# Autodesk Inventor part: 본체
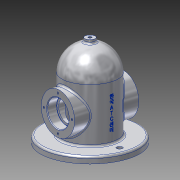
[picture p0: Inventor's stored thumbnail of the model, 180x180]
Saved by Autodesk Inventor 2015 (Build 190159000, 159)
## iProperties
Created: 2019-11
Part Number: 본체
Material: 알루미늄 6061
Document SubType Name: Modeling
Designer: LINEART-SSD.D4.16.06
Density: 2.7 g/cm^3
Appearance: 알루미늄 - 평지
Mass: 1106.13 g
Surface Area: 883.263 cm^2
Volume: 409.676 cm^3
Author: LINEART-SSD.D4.16.06
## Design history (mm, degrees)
sketch "스케치1"
  geometry: C1 r 70 at (0, 0); 1 further point
  constraints: 1 centre point, 1 coincident
  dimensions: "d0" = 140 diameter of C1
extrude "돌출1" new body sketch "스케치1" distance "d1" = 10; taper "d2" = 0 deg
sketch "스케치2"
  geometry: L1 (81, 50)-(50, 50); L2 (50, 50)-(50, -50); L3 (50, -50)-(81, -50); L4 (81, -50)-(81, 50); 2 further points
  constraints: 8 end point, 2 parallel, 1 horizontal, 1 horizontal alignment, 1 midpoint, 1 perpendicular
  dimensions: "d3" = 50 distance from line of L2 point (0, 0); "d4" = 100 distance of L3.end L1.start; "d5" = 62 diameter of L4 L2
revolve "회전1" sketch "스케치2" stored, may be unused: angle "d6" = 90 deg
sketch "스케치3"
  geometry: C1 r 40 at (0, 0); 1 further point
  constraints: 1 centre point, 1 coincident
  dimensions: "d7" = 80 diameter of C1
extrude "돌출2" join sketch "스케치3" distance "d8" = 80; taper "d9" = 0 deg
sketch "스케치4"
  geometry: L1 (90, -40)-(90, 40) reference; L2 (90, 0)-(130, 0); L3 (90, 0)-(90, -40); L4 (130, 0)-(90, 0); L5 (90, 0)-(90, -40); A1 r 40 centre (90, 0) between (90, -40) and (130, 0); 1 further point
  constraints: 8 end point, 2 point on circle, 1 centre point, 1 collinear, 1 horizontal alignment, 1 midpoint, 1 point on line
  dimensions: "d10" = 40 radius of A1; "d11" = 90 deg angle of L3 L2
revolve "회전2" sketch "스케치4" stored, may be unused: angle "d12" = 90 deg
sketch "스케치5"
  geometry: C1 r 30 at (0, 0); 1 further point
  constraints: 1 centre point, 1 coincident
  dimensions: "d13" = 60 diameter of C1
extrude "돌출3" cut sketch "스케치5" distance "d14" = 90; taper "d15" = 0 deg
sketch "스케치6"
  geometry: L1 (90, -30)-(90, 30) reference; L2 (0, -30)-(0, 30) reference; L3 (90, 0)-(120, 0); L4 (90, 0)-(90, -30); L5 (120, 0)-(90, 0); L6 (90, 0)-(90, -30); A1 r 30 centre (90, 0) between (90, -30) and (120, 0); 1 further point
  constraints: 8 end point, 2 point on circle, 1 centre point, 1 collinear, 1 midpoint
  dimensions: "d16" = 30 radius of A1 (derived); "d17" = 90 deg angle of L4 L3
revolve "회전3" sketch "스케치6" stored, may be unused: angle "d18" = 90 deg
sketch "스케치7"
  geometry: L1 (70, 50)-(70, 35.3); L2 (69.7, 35)-(66.5, 35); L3 (66.5, 35)-(66.5, -35); L4 (66.5, -35)-(69.7, -35); L5 (0, -30)-(90, -30) reference; L6 (70, -35.3)-(70, -50); L7 (70, -50)-(50, -50); L8 (50, -50)-(50, 50); L9 (50, 50)-(70, 50); A1 r 0.3 centre (69.7, 35.3) between (69.7, 35) and (70, 35.3); A2 r 0.3 centre (69.7, -35.3) between (70, -35.3) and (69.7, -35); 4 further points
  constraints: 16 end point, 6 perpendicular, 4 point on circle, 4 point on line, 4 tangent, 2 centre point, 1 equal radius, 1 horizontal alignment, 1 midpoint, 1 parallel, 1 vertical
  dimensions: "d19" = 15 distance of L1.start point (70, 35); "d20" = 15 distance of point (70, -35) L6.end; "d21" = 100 distance of L7.end L8.end; "d22" = 50 distance from line of point (0, 0) L8; "d23" = 33 diameter of L3 L8; "d24" = 40 diameter of L1 L8; "d25" = 40 diameter of L6 L8; "d26" = 0.3 radius of A1
revolve "회전4" sketch "스케치7" stored, may be unused: angle "d27" = 90 deg
sketch "스케치8"
  geometry: C1 r 20 at (0, 0) reference; C2 r 31 at (0, 0) reference; 2 further points
  constraints: 1 vertical alignment
  dimensions: "d28" = 26 distance of point (0, 26) C1.centre
hole "구멍1" sketch "스케치8" at (0, 26) diameter "d29" = 3.242; stored, may be unused: countersink angle "d33" = 90 deg, drill point angle "d35" = 118 deg; dims "d30" = 8, "d31" = 4, "d32" = 2, "d34" = 10
node "작업 평면1"
node "작업 평면2"
sketch "스케치9"
  geometry: C1 r 7.5 at (0, 0); 1 further point
  constraints: 1 centre point, 1 coincident
  dimensions: "d39" = 15 diameter of C1
extrude "돌출4" join sketch "스케치9" stored distance "d40" = 10; taper "d41" = 0 deg
sketch "스케치10"
  geometry: C1 r 7.5 at (0, 0) reference; 2 further points
  constraints: 1 coincident
hole "구멍2" sketch "스케치10" at (0, 0) diameter "d42" = 5.188; stored, may be unused: countersink angle "d46" = 90 deg, drill point angle "d48" = 118 deg; dims "d43" = 12, "d44" = 4, "d45" = 2, "d47" = 16
sketch "스케치11"
  geometry: C1 r 70 at (0, 0) reference; 2 further points
  constraints: 1 horizontal alignment
  dimensions: "d49" = 55 distance of point (0, 0) point (-55, 0)
hole "구멍3" sketch "스케치11" at (-55, 0) diameter "d50" = 9; stored, may be unused: countersink angle "d54" = 90 deg, drill point angle "d56" = 118 deg; dims "d51" = 12, "d52" = 4, "d53" = 2, "d55" = 16
node "작업 평면3"
sketch "스케치12"
  geometry: L1 (-10, 70)-(-10, -70) reference; 2 further points
  constraints: 1 horizontal alignment, 1 other
  dimensions: "d60" = 50 distance from line of L1 point (40, 0)
feature "엠보싱1" sketch "스케치12" dims "d1" = 10, "d2" = 0, "d61" = 0.5, "d62" = 0
chamfer "모따기1" distance "d63" = 1; stored, may be unused: second distance "d64" = 2, angle "d65" = 45 deg
chamfer "모따기2" distance "d66" = 1; stored, may be unused: second distance "d67" = 2, angle "d68" = 45 deg
fillet "모깎기1" dims "d69" = 3
node "솔리드1"
pattern_circular "원형 패턴1" dims angle "d37" = 360 deg
mirror "대칭1"
pattern_circular "원형 패턴2" dims angle "d58" = 360 deg
node "투영된 루프1"
node "투영된 루프2"
